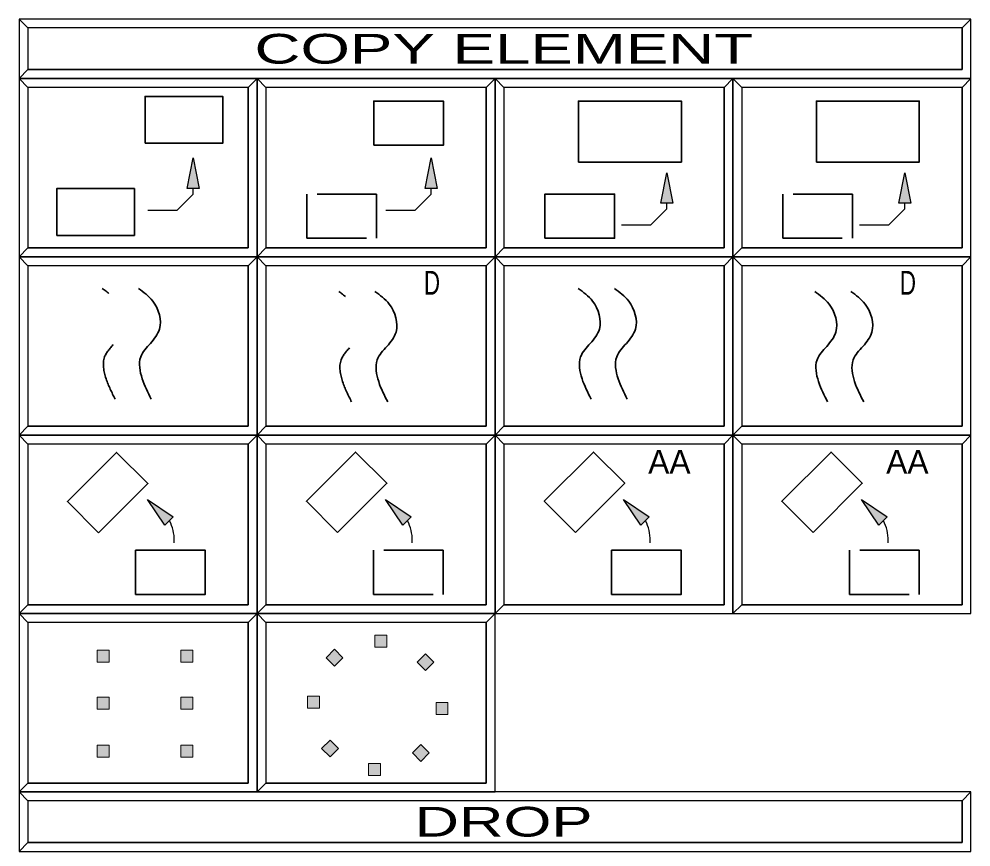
# Model space of a CAD drawing. Extents: x 95906.9 to 95918.9, y 90964.8 to 90972.9.
# Drawn here: x 95912.632 to 95914.232, y 90966.869 to 90968.262 of the extents above; entities that cross this region are included whole.
import ezdxf
from ezdxf.enums import TextEntityAlignment as Align

# ---------------------------------------------------------------- set-up
doc = ezdxf.new("R2010")
doc.units = 0
doc.header["$LTSCALE"] = 0.019
doc.linetypes.add('MEDIUM_DASHED', pattern=[4.5, 3, -1.5])
for name, color, linetype, lineweight in [('1', 7, 'Continuous', 25), ('11', 7, 'Continuous', 25), ('18', 7, 'Continuous', 25), ('2', 7, 'Continuous', 13), ('3', 7, 'Continuous', 25), ('4', 7, 'Continuous', 35), ('6', 7, 'Continuous', 35), ('7', 7, 'Continuous', 35)]:
    doc.layers.add(name, color=color, linetype=linetype, lineweight=lineweight)

msp = doc.modelspace()

# ---------------------------------------------------------------- hatches: boundary and pattern name
at = {"layer": '6'}
for points in [[(95912.9149, 90967.9769), (95912.9251, 90968.0281), (95912.9353, 90967.9769)], [(95913.3149, 90967.9769), (95913.3251, 90968.0281), (95913.3353, 90967.9769)], [(95913.711, 90967.9519), (95913.7212, 90968.0031), (95913.7314, 90967.9519)], [(95914.111, 90967.9519), (95914.1212, 90968.0031), (95914.1314, 90967.9519)], [(95912.8772, 90967.4102), (95912.8482, 90967.4536), (95912.8916, 90967.4246)], [(95913.2772, 90967.4102), (95913.2482, 90967.4536), (95913.2916, 90967.4246)], [(95913.6772, 90967.4102), (95913.6482, 90967.4536), (95913.6916, 90967.4246)], [(95914.0772, 90967.4102), (95914.0482, 90967.4536), (95914.0916, 90967.4246)], [(95913.2305, 90967.2054), (95913.2505, 90967.2054), (95913.2505, 90967.2254), (95913.2305, 90967.2254)], [(95912.7636, 90967.1801), (95912.7836, 90967.1801), (95912.7836, 90967.2001), (95912.7636, 90967.2001)], [(95912.9043, 90967.1801), (95912.9243, 90967.1801), (95912.9243, 90967.2001), (95912.9043, 90967.2001)], [(95913.1626, 90967.1734), (95913.1767, 90967.1875), (95913.1626, 90967.2017), (95913.1485, 90967.1875)], [(95913.3012, 90967.18), (95913.3153, 90967.1659), (95913.3295, 90967.18), (95913.3153, 90967.1941)], [(95912.7636, 90967.101), (95912.7836, 90967.101), (95912.7836, 90967.121), (95912.7636, 90967.121)], [(95912.9043, 90967.101), (95912.9243, 90967.101), (95912.9243, 90967.121), (95912.9043, 90967.121)], [(95913.1372, 90967.1027), (95913.1372, 90967.1227), (95913.1172, 90967.1227), (95913.1172, 90967.1027)], [(95913.3332, 90967.1121), (95913.3332, 90967.0921), (95913.3532, 90967.0921), (95913.3532, 90967.1121)], [(95912.7636, 90967.0204), (95912.7836, 90967.0204), (95912.7836, 90967.0404), (95912.7636, 90967.0404)], [(95912.9043, 90967.0204), (95912.9243, 90967.0204), (95912.9243, 90967.0404), (95912.9043, 90967.0404)], [(95913.1692, 90967.0348), (95913.1551, 90967.0489), (95913.1409, 90967.0348), (95913.1551, 90967.0207)], [(95913.3078, 90967.0414), (95913.2937, 90967.0273), (95913.3078, 90967.0131), (95913.3219, 90967.0273)], [(95913.2399, 90967.0094), (95913.2199, 90967.0094), (95913.2199, 90966.9894), (95913.2399, 90966.9894)]]:
    msp.add_hatch(color=256, dxfattribs=at).paths.add_polyline_path(points)

# ---------------------------------------------------------------- linework, layer by layer
at = {"layer": '1'}
for points in [[(95912.6323, 90968.1617), (95914.2323, 90968.1617), (95914.2323, 90968.2617), (95912.6323, 90968.2617)], [(95912.6323, 90967.8617), (95913.0323, 90967.8617), (95913.0323, 90968.1617), (95912.6323, 90968.1617)], [(95913.0323, 90967.8617), (95913.4323, 90967.8617), (95913.4323, 90968.1617), (95913.0323, 90968.1617)], [(95913.4323, 90967.8617), (95913.8323, 90967.8617), (95913.8323, 90968.1617), (95913.4323, 90968.1617)], [(95913.8323, 90967.8617), (95914.2323, 90967.8617), (95914.2323, 90968.1617), (95913.8323, 90968.1617)], [(95912.6323, 90967.5617), (95913.0323, 90967.5617), (95913.0323, 90967.8617), (95912.6323, 90967.8617)], [(95913.0323, 90967.5617), (95913.4323, 90967.5617), (95913.4323, 90967.8617), (95913.0323, 90967.8617)], [(95913.4323, 90967.5617), (95913.8323, 90967.5617), (95913.8323, 90967.8617), (95913.4323, 90967.8617)], [(95913.8323, 90967.5617), (95914.2323, 90967.5617), (95914.2323, 90967.8617), (95913.8323, 90967.8617)], [(95912.6323, 90967.2617), (95913.0323, 90967.2617), (95913.0323, 90967.5617), (95912.6323, 90967.5617)], [(95913.0323, 90967.2617), (95913.4323, 90967.2617), (95913.4323, 90967.5617), (95913.0323, 90967.5617)], [(95913.4323, 90967.2617), (95913.8323, 90967.2617), (95913.8323, 90967.5617), (95913.4323, 90967.5617)], [(95913.8323, 90967.2617), (95914.2323, 90967.2617), (95914.2323, 90967.5617), (95913.8323, 90967.5617)], [(95912.6323, 90966.9617), (95913.0323, 90966.9617), (95913.0323, 90967.2617), (95912.6323, 90967.2617)], [(95913.0323, 90966.9617), (95913.4323, 90966.9617), (95913.4323, 90967.2617), (95913.0323, 90967.2617)], [(95912.6323, 90966.8617), (95914.2323, 90966.8617), (95914.2323, 90966.9617), (95912.6323, 90966.9617)]]:
    msp.add_lwpolyline(points, close=True, dxfattribs=at)
at = {"layer": '11'}
for points in [[(95912.6473, 90967.8767), (95913.0173, 90967.8767), (95913.0173, 90968.1467), (95912.6473, 90968.1467)], [(95913.0473, 90967.8767), (95913.4173, 90967.8767), (95913.4173, 90968.1467), (95913.0473, 90968.1467)], [(95913.4473, 90967.8767), (95913.8173, 90967.8767), (95913.8173, 90968.1467), (95913.4473, 90968.1467)], [(95913.8473, 90967.8767), (95914.2173, 90967.8767), (95914.2173, 90968.1467), (95913.8473, 90968.1467)], [(95912.6473, 90967.5767), (95913.0173, 90967.5767), (95913.0173, 90967.8467), (95912.6473, 90967.8467)], [(95913.0473, 90967.5767), (95913.4173, 90967.5767), (95913.4173, 90967.8467), (95913.0473, 90967.8467)], [(95913.4473, 90967.5767), (95913.8173, 90967.5767), (95913.8173, 90967.8467), (95913.4473, 90967.8467)], [(95913.8473, 90967.5767), (95914.2173, 90967.5767), (95914.2173, 90967.8467), (95913.8473, 90967.8467)], [(95912.6473, 90967.2767), (95913.0173, 90967.2767), (95913.0173, 90967.5467), (95912.6473, 90967.5467)], [(95913.0473, 90967.2767), (95913.4173, 90967.2767), (95913.4173, 90967.5467), (95913.0473, 90967.5467)], [(95913.4473, 90967.2767), (95913.8173, 90967.2767), (95913.8173, 90967.5467), (95913.4473, 90967.5467)], [(95913.8473, 90967.2767), (95914.2173, 90967.2767), (95914.2173, 90967.5467), (95913.8473, 90967.5467)], [(95912.6473, 90966.9767), (95913.0173, 90966.9767), (95913.0173, 90967.2467), (95912.6473, 90967.2467)], [(95913.0473, 90966.9767), (95913.4173, 90966.9767), (95913.4173, 90967.2467), (95913.0473, 90967.2467)]]:
    msp.add_lwpolyline(points, close=True, dxfattribs=at)
at = {"layer": '18'}
for points in [[(95912.6473, 90968.1767), (95914.2173, 90968.1767), (95914.2173, 90968.2467), (95912.6473, 90968.2467)], [(95912.6473, 90966.8767), (95914.2173, 90966.8767), (95914.2173, 90966.9467), (95912.6473, 90966.9467)]]:
    msp.add_lwpolyline(points, close=True, dxfattribs=at)
at = {"layer": '2'}
for points in [[(95912.6323, 90968.2617), (95912.6323, 90968.1617), (95912.6473, 90968.1767), (95912.6473, 90968.2467), (95914.2173, 90968.2467), (95914.2323, 90968.2617)], [(95912.6323, 90968.1617), (95912.6323, 90967.8617), (95912.6473, 90967.8767), (95912.6473, 90968.1467), (95913.0173, 90968.1467), (95913.0323, 90968.1617)], [(95913.0323, 90968.1617), (95913.0323, 90967.8617), (95913.0473, 90967.8767), (95913.0473, 90968.1467), (95913.4173, 90968.1467), (95913.4323, 90968.1617)], [(95913.4323, 90968.1617), (95913.4323, 90967.8617), (95913.4473, 90967.8767), (95913.4473, 90968.1467), (95913.8173, 90968.1467), (95913.8323, 90968.1617)], [(95913.8323, 90968.1617), (95913.8323, 90967.8617), (95913.8473, 90967.8767), (95913.8473, 90968.1467), (95914.2173, 90968.1467), (95914.2323, 90968.1617)], [(95912.6323, 90967.8617), (95912.6323, 90967.5617), (95912.6473, 90967.5767), (95912.6473, 90967.8467), (95913.0173, 90967.8467), (95913.0323, 90967.8617)], [(95913.0323, 90967.8617), (95913.0323, 90967.5617), (95913.0473, 90967.5767), (95913.0473, 90967.8467), (95913.4173, 90967.8467), (95913.4323, 90967.8617)], [(95913.4323, 90967.8617), (95913.4323, 90967.5617), (95913.4473, 90967.5767), (95913.4473, 90967.8467), (95913.8173, 90967.8467), (95913.8323, 90967.8617)], [(95913.8323, 90967.8617), (95913.8323, 90967.5617), (95913.8473, 90967.5767), (95913.8473, 90967.8467), (95914.2173, 90967.8467), (95914.2323, 90967.8617)], [(95912.6323, 90967.5617), (95912.6323, 90967.2617), (95912.6473, 90967.2767), (95912.6473, 90967.5467), (95913.0173, 90967.5467), (95913.0323, 90967.5617)], [(95913.0323, 90967.5617), (95913.0323, 90967.2617), (95913.0473, 90967.2767), (95913.0473, 90967.5467), (95913.4173, 90967.5467), (95913.4323, 90967.5617)], [(95913.4323, 90967.5617), (95913.4323, 90967.2617), (95913.4473, 90967.2767), (95913.4473, 90967.5467), (95913.8173, 90967.5467), (95913.8323, 90967.5617)], [(95913.8323, 90967.5617), (95913.8323, 90967.2617), (95913.8473, 90967.2767), (95913.8473, 90967.5467), (95914.2173, 90967.5467), (95914.2323, 90967.5617)], [(95912.6323, 90967.2617), (95912.6323, 90966.9617), (95912.6473, 90966.9767), (95912.6473, 90967.2467), (95913.0173, 90967.2467), (95913.0323, 90967.2617)], [(95913.0323, 90967.2617), (95913.0323, 90966.9617), (95913.0473, 90966.9767), (95913.0473, 90967.2467), (95913.4173, 90967.2467), (95913.4323, 90967.2617)], [(95912.6323, 90966.9617), (95912.6323, 90966.8617), (95912.6473, 90966.8767), (95912.6473, 90966.9467), (95914.2173, 90966.9467), (95914.2323, 90966.9617)]]:
    msp.add_lwpolyline(points, close=True, dxfattribs=at)
at = {"layer": '3'}
for points in [[(95912.6323, 90968.1617), (95914.2323, 90968.1617), (95914.2323, 90968.2617), (95914.2173, 90968.2467), (95914.2173, 90968.1767), (95912.6473, 90968.1767)], [(95912.6323, 90967.8617), (95913.0323, 90967.8617), (95913.0323, 90968.1617), (95913.0173, 90968.1467), (95913.0173, 90967.8767), (95912.6473, 90967.8767)], [(95913.0323, 90967.8617), (95913.4323, 90967.8617), (95913.4323, 90968.1617), (95913.4173, 90968.1467), (95913.4173, 90967.8767), (95913.0473, 90967.8767)], [(95913.4323, 90967.8617), (95913.8323, 90967.8617), (95913.8323, 90968.1617), (95913.8173, 90968.1467), (95913.8173, 90967.8767), (95913.4473, 90967.8767)], [(95913.8323, 90967.8617), (95914.2323, 90967.8617), (95914.2323, 90968.1617), (95914.2173, 90968.1467), (95914.2173, 90967.8767), (95913.8473, 90967.8767)], [(95912.6323, 90967.5617), (95913.0323, 90967.5617), (95913.0323, 90967.8617), (95913.0173, 90967.8467), (95913.0173, 90967.5767), (95912.6473, 90967.5767)], [(95913.0323, 90967.5617), (95913.4323, 90967.5617), (95913.4323, 90967.8617), (95913.4173, 90967.8467), (95913.4173, 90967.5767), (95913.0473, 90967.5767)], [(95913.4323, 90967.5617), (95913.8323, 90967.5617), (95913.8323, 90967.8617), (95913.8173, 90967.8467), (95913.8173, 90967.5767), (95913.4473, 90967.5767)], [(95913.8323, 90967.5617), (95914.2323, 90967.5617), (95914.2323, 90967.8617), (95914.2173, 90967.8467), (95914.2173, 90967.5767), (95913.8473, 90967.5767)], [(95912.6323, 90967.2617), (95913.0323, 90967.2617), (95913.0323, 90967.5617), (95913.0173, 90967.5467), (95913.0173, 90967.2767), (95912.6473, 90967.2767)], [(95913.0323, 90967.2617), (95913.4323, 90967.2617), (95913.4323, 90967.5617), (95913.4173, 90967.5467), (95913.4173, 90967.2767), (95913.0473, 90967.2767)], [(95913.4323, 90967.2617), (95913.8323, 90967.2617), (95913.8323, 90967.5617), (95913.8173, 90967.5467), (95913.8173, 90967.2767), (95913.4473, 90967.2767)], [(95913.8323, 90967.2617), (95914.2323, 90967.2617), (95914.2323, 90967.5617), (95914.2173, 90967.5467), (95914.2173, 90967.2767), (95913.8473, 90967.2767)], [(95912.6323, 90966.9617), (95913.0323, 90966.9617), (95913.0323, 90967.2617), (95913.0173, 90967.2467), (95913.0173, 90966.9767), (95912.6473, 90966.9767)], [(95913.0323, 90966.9617), (95913.4323, 90966.9617), (95913.4323, 90967.2617), (95913.4173, 90967.2467), (95913.4173, 90966.9767), (95913.0473, 90966.9767)], [(95912.6323, 90966.8617), (95914.2323, 90966.8617), (95914.2323, 90966.9617), (95914.2173, 90966.9467), (95914.2173, 90966.8767), (95912.6473, 90966.8767)]]:
    msp.add_lwpolyline(points, close=True, dxfattribs=at)
at = {"layer": '4'}
for p, q in [((95912.6473, 90968.2467), (95912.6323, 90968.2617)), ((95912.6473, 90968.1467), (95912.6323, 90968.1617)), ((95913.0473, 90968.1467), (95913.0323, 90968.1617)), ((95913.4473, 90968.1467), (95913.4323, 90968.1617)), ((95913.8473, 90968.1467), (95913.8323, 90968.1617)), ((95912.6473, 90967.8467), (95912.6323, 90967.8617)), ((95913.0473, 90967.8467), (95913.0323, 90967.8617)), ((95913.4473, 90967.8467), (95913.4323, 90967.8617)), ((95913.8473, 90967.8467), (95913.8323, 90967.8617)), ((95912.6473, 90967.5467), (95912.6323, 90967.5617)), ((95913.0473, 90967.5467), (95913.0323, 90967.5617)), ((95913.4473, 90967.5467), (95913.4323, 90967.5617)), ((95913.8473, 90967.5467), (95913.8323, 90967.5617)), ((95912.6473, 90967.2467), (95912.6323, 90967.2617)), ((95913.0473, 90967.2467), (95913.0323, 90967.2617)), ((95912.6473, 90966.9467), (95912.6323, 90966.9617))]:
    msp.add_line(p, q, dxfattribs=at)
at = {"layer": '6', "lineweight": 25}
for p, q in [((95912.8933, 90967.381), (95912.8933, 90967.3844)), ((95913.2933, 90967.381), (95913.2933, 90967.3844)), ((95913.6933, 90967.381), (95913.6933, 90967.3844)), ((95914.0933, 90967.381), (95914.0933, 90967.3844))]:
    msp.add_line(p, q, dxfattribs=at)
at = {"layer": '6'}
for points in [[(95912.8442, 90968.0528), (95912.9747, 90968.0528), (95912.9747, 90968.1315), (95912.8442, 90968.1315)], [(95913.2284, 90968.0495), (95913.3455, 90968.0495), (95913.3455, 90968.1238), (95913.2284, 90968.1238)], [(95913.5724, 90968.021), (95913.7455, 90968.021), (95913.7455, 90968.1238), (95913.5724, 90968.1238)], [(95913.9724, 90968.021), (95914.1455, 90968.021), (95914.1455, 90968.1238), (95913.9724, 90968.1238)], [(95912.6957, 90967.8977), (95912.8262, 90967.8977), (95912.8262, 90967.9764), (95912.6957, 90967.9764)], [(95913.5161, 90967.8929), (95913.6332, 90967.8929), (95913.6332, 90967.9672), (95913.5161, 90967.9672)], [(95912.766, 90967.3975), (95912.8488, 90967.4803), (95912.7963, 90967.5328), (95912.7135, 90967.45)], [(95913.1677, 90967.3981), (95913.2505, 90967.4809), (95913.198, 90967.5334), (95913.1152, 90967.4506)], [(95913.5677, 90967.3981), (95913.6505, 90967.4809), (95913.598, 90967.5334), (95913.5152, 90967.4506)], [(95913.9668, 90967.3981), (95914.0496, 90967.4809), (95913.9971, 90967.5334), (95913.9143, 90967.4506)], [(95912.8283, 90967.294), (95912.9454, 90967.294), (95912.9454, 90967.3683), (95912.8283, 90967.3683)], [(95913.6283, 90967.294), (95913.7454, 90967.294), (95913.7454, 90967.3683), (95913.6283, 90967.3683)]]:
    msp.add_lwpolyline(points, close=True, dxfattribs=at)
at = {"layer": '6', "lineweight": 25}
for points in [[(95912.9149, 90967.9769), (95912.9251, 90968.0281), (95912.9353, 90967.9769)], [(95913.3149, 90967.9769), (95913.3251, 90968.0281), (95913.3353, 90967.9769)], [(95913.711, 90967.9519), (95913.7212, 90968.0031), (95913.7314, 90967.9519)], [(95914.111, 90967.9519), (95914.1212, 90968.0031), (95914.1314, 90967.9519)], [(95912.8772, 90967.4102), (95912.8482, 90967.4536), (95912.8916, 90967.4246)], [(95913.2772, 90967.4102), (95913.2482, 90967.4536), (95913.2916, 90967.4246)], [(95913.6772, 90967.4102), (95913.6482, 90967.4536), (95913.6916, 90967.4246)], [(95914.0772, 90967.4102), (95914.0482, 90967.4536), (95914.0916, 90967.4246)]]:
    msp.add_lwpolyline(points, close=True, dxfattribs=at)
for points in [[(95912.8487, 90967.9404), (95912.8982, 90967.9404), (95912.9251, 90967.9673), (95912.9251, 90967.9769)], [(95913.2487, 90967.9404), (95913.2982, 90967.9404), (95913.3251, 90967.9673), (95913.3251, 90967.9769)], [(95913.6448, 90967.9154), (95913.6943, 90967.9154), (95913.7212, 90967.9423), (95913.7212, 90967.9519)], [(95914.0448, 90967.9154), (95914.0943, 90967.9154), (95914.1212, 90967.9423), (95914.1212, 90967.9519)]]:
    msp.add_lwpolyline(points, dxfattribs=at)
at = {"layer": '6', "linetype": 'MEDIUM_DASHED'}
for points in [[(95913.1161, 90967.8929), (95913.2332, 90967.8929), (95913.2332, 90967.9672), (95913.1161, 90967.9672)], [(95913.9161, 90967.8929), (95914.0332, 90967.8929), (95914.0332, 90967.9672), (95913.9161, 90967.9672)], [(95913.2283, 90967.294), (95913.3454, 90967.294), (95913.3454, 90967.3683), (95913.2283, 90967.3683)], [(95914.0283, 90967.294), (95914.1454, 90967.294), (95914.1454, 90967.3683), (95914.0283, 90967.3683)]]:
    msp.add_lwpolyline(points, close=True, dxfattribs=at)
at = {"layer": '6', "lineweight": 13}
for points in [[(95913.2305, 90967.2054), (95913.2505, 90967.2054), (95913.2505, 90967.2254), (95913.2305, 90967.2254)], [(95912.7636, 90967.1801), (95912.7836, 90967.1801), (95912.7836, 90967.2001), (95912.7636, 90967.2001)], [(95912.9043, 90967.1801), (95912.9243, 90967.1801), (95912.9243, 90967.2001), (95912.9043, 90967.2001)], [(95913.1626, 90967.1734), (95913.1767, 90967.1875), (95913.1626, 90967.2017), (95913.1485, 90967.1875)], [(95913.3012, 90967.18), (95913.3153, 90967.1659), (95913.3295, 90967.18), (95913.3153, 90967.1941)], [(95912.7636, 90967.101), (95912.7836, 90967.101), (95912.7836, 90967.121), (95912.7636, 90967.121)], [(95912.9043, 90967.101), (95912.9243, 90967.101), (95912.9243, 90967.121), (95912.9043, 90967.121)], [(95913.1372, 90967.1027), (95913.1372, 90967.1227), (95913.1172, 90967.1227), (95913.1172, 90967.1027)], [(95913.3332, 90967.1121), (95913.3332, 90967.0921), (95913.3532, 90967.0921), (95913.3532, 90967.1121)], [(95912.7636, 90967.0204), (95912.7836, 90967.0204), (95912.7836, 90967.0404), (95912.7636, 90967.0404)], [(95912.9043, 90967.0204), (95912.9243, 90967.0204), (95912.9243, 90967.0404), (95912.9043, 90967.0404)], [(95913.1692, 90967.0348), (95913.1551, 90967.0489), (95913.1409, 90967.0348), (95913.1551, 90967.0207)], [(95913.3078, 90967.0414), (95913.2937, 90967.0273), (95913.3078, 90967.0131), (95913.3219, 90967.0273)], [(95913.2399, 90967.0094), (95913.2199, 90967.0094), (95913.2199, 90966.9894), (95913.2399, 90966.9894)]]:
    msp.add_lwpolyline(points, close=True, dxfattribs=at)
at = {"layer": '6', "lineweight": 25}
for centre in [(95912.8183, 90967.3844), (95913.2183, 90967.3844), (95913.6183, 90967.3844), (95914.0183, 90967.3844)]:
    msp.add_arc(centre, 0.075, 0, 26.5009, dxfattribs=at)
at = {"layer": '6', "linetype": 'MEDIUM_DASHED'}
for points in [[(95912.7938, 90967.6226), (95912.7786, 90967.6568), (95912.7761, 90967.6934), (95912.7925, 90967.7162), (95912.8077, 90967.7402), (95912.7963, 90967.7871), (95912.7722, 90967.8085)], [(95913.1913, 90967.6176), (95913.1761, 90967.6518), (95913.1736, 90967.6884), (95913.19, 90967.7112), (95913.2052, 90967.7352), (95913.1938, 90967.7821), (95913.1697, 90967.8035)]]:
    msp.add_spline(points, degree=3, dxfattribs=at)
at = {"layer": '6'}
for points in [[(95912.8545, 90967.6226), (95912.8393, 90967.6568), (95912.8368, 90967.6934), (95912.8532, 90967.7162), (95912.8684, 90967.7402), (95912.857, 90967.7871), (95912.833, 90967.8085)], [(95913.5938, 90967.6226), (95913.5786, 90967.6568), (95913.5761, 90967.6934), (95913.5925, 90967.7162), (95913.6077, 90967.7402), (95913.5963, 90967.7871), (95913.5722, 90967.8085)], [(95913.6545, 90967.6226), (95913.6393, 90967.6568), (95913.6368, 90967.6934), (95913.6532, 90967.7162), (95913.6684, 90967.7402), (95913.657, 90967.7871), (95913.633, 90967.8085)], [(95913.252, 90967.6176), (95913.2368, 90967.6518), (95913.2343, 90967.6884), (95913.2507, 90967.7112), (95913.2659, 90967.7352), (95913.2545, 90967.7821), (95913.2305, 90967.8035)], [(95913.9913, 90967.6176), (95913.9761, 90967.6518), (95913.9736, 90967.6884), (95913.99, 90967.7112), (95914.0052, 90967.7352), (95913.9938, 90967.7821), (95913.9697, 90967.8035)], [(95914.052, 90967.6176), (95914.0368, 90967.6518), (95914.0343, 90967.6884), (95914.0507, 90967.7112), (95914.0659, 90967.7352), (95914.0545, 90967.7821), (95914.0305, 90967.8035)]]:
    msp.add_spline(points, degree=3, dxfattribs=at)

# ---------------------------------------------------------------- texts
at = {"layer": '6', "width": 0.7}
for p in [(95913.3264, 90967.7981), (95914.1264, 90967.7981)]:
    msp.add_text('D', height=0.04, dxfattribs=at).set_placement(p, align=Align.CENTER)
at = {"layer": '6'}
for p in [(95913.7254, 90967.497), (95914.1254, 90967.497)]:
    msp.add_text('AA', height=0.04, dxfattribs=at).set_placement(p, align=Align.CENTER)
at = {"layer": '7'}
for s, width, p in [('      COPY ELEMENT     ', 1.6, (95913.4322, 90968.1867)), ('          DROP         ', 1.55, (95913.4322, 90966.8867))]:
    msp.add_text(s, height=0.04999, dxfattribs=dict(at, width=width)).set_placement(p, align=Align.CENTER)

doc.saveas('drawing.dxf')
